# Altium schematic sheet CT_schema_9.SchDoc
size 274 x 160 mm
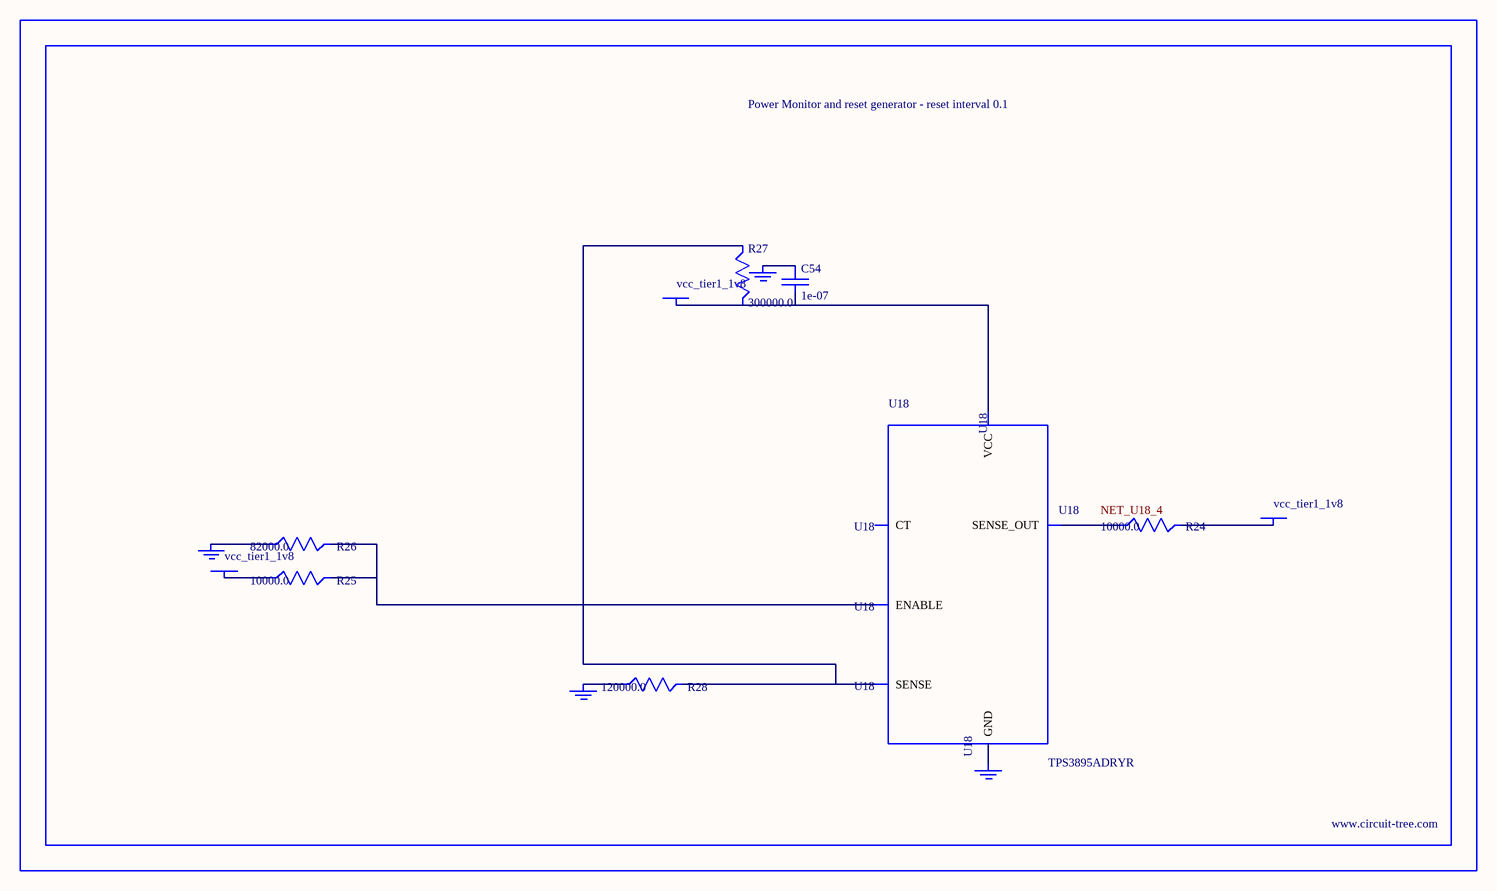
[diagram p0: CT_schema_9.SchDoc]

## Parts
BORDER8  (no value)
C54  1e-07  [C0402]
GND_INSTANCE_8_0  (no value)
GND_INSTANCE_8_1  (no value)
GND_INSTANCE_8_2  (no value)
GND_INSTANCE_8_3  (no value)
POWER_INSTANCE_8_0  vcc_tier1_1v8
POWER_INSTANCE_8_1  vcc_tier1_1v8
POWER_INSTANCE_8_2  vcc_tier1_1v8
R24  10000.0  [R0603]
R25  10000.0  [R0603]
R26  82000.0  [R0603]
R27  300000.0  [R0603]
R28  120000.0  [R0603]
U18  TPS3895ADRYR  [SON-6]

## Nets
NetC54_1: C54.1 GND_INSTANCE_8_2.0(GND)
NetC54_2: C54.2 POWER_INSTANCE_8_2.0(PWR) R27.2 U18.6(VCC)
NetGND_INSTANCE_8_0_0: GND_INSTANCE_8_0.0(GND) R26.1
NetGND_INSTANCE_8_1_0: GND_INSTANCE_8_1.0(GND) R28.1
NetGND_INSTANCE_8_3_0: GND_INSTANCE_8_3.0(GND) U18.2(GND)
NetPOWER_INSTANCE_8_0_0: POWER_INSTANCE_8_0.0(PWR) R25.1
NetPOWER_INSTANCE_8_1_0: POWER_INSTANCE_8_1.0(PWR) R24.2
NetR24_1: R24.1 U18.4(SENSE_OUT)
NetR25_2: R25.2 R26.2 U18.1(ENABLE)
NetR27_1: R27.1 R28.2 U18.3(SENSE)

Not connected (* = marked no-connect by the designer): U18 5(CT)

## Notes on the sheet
- Labels drawn without touching a wire or pin: NET_U18_4

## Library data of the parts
BORDER8 = BORDER_PAGE8
C54 = C0402C104K3RACTU
GND_INSTANCE_8_0-GND_INSTANCE_8_3 = GND
POWER_INSTANCE_8_0-POWER_INSTANCE_8_2 = PWR
R24 R25 = RC0603JR-0710KL
R26 = RC0603JR-0782KL
R27 = RC0603JR-07300KL
R28 = RC0603JR-07120KL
